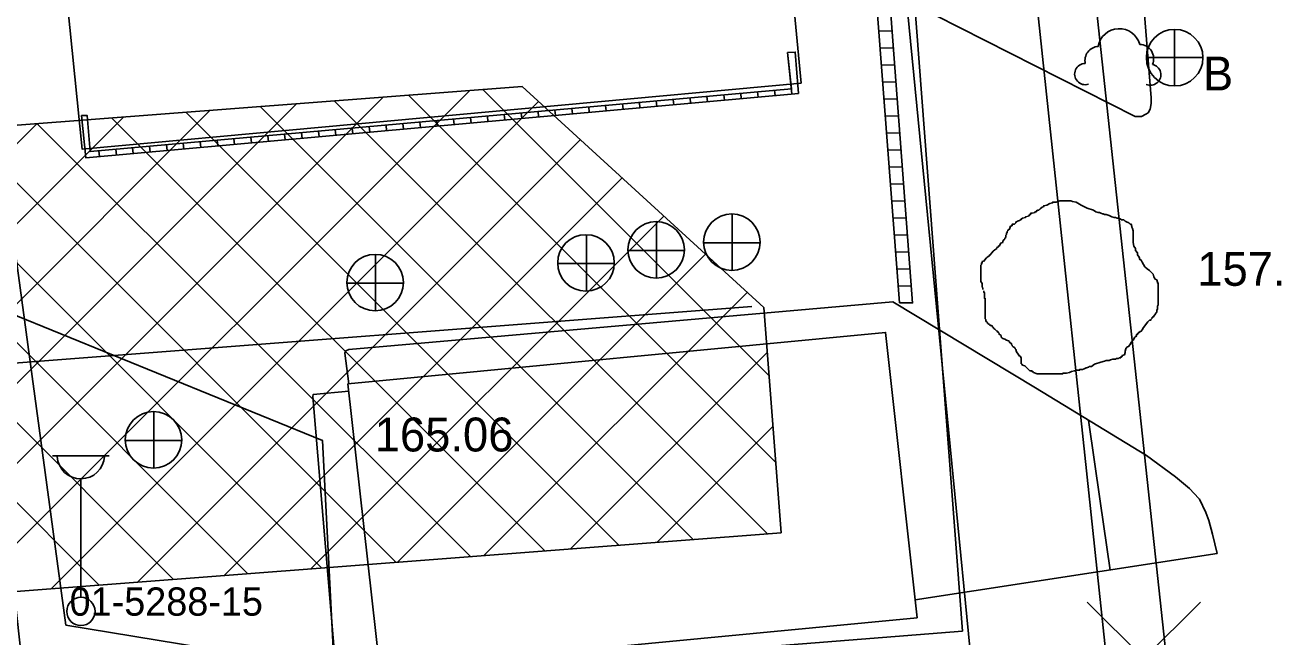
# Model space of a CAD drawing. Extents: x 419101 to 420177, y 4451541 to 4452254.
# Drawn here: x 419933.36 to 419977.69, y 4451769.46 to 4451791.12 of the extents above; entities that cross this region are included whole.
import ezdxf

# ---------------------------------------------------------------- set-up
doc = ezdxf.new("R2010")
doc.units = 0
for name, color, linetype in [('2_KADASTRO', 7, 'Continuous'), ('3_HALİHAZIR', 7, 'Continuous'), ('Level 10', 7, 'Continuous'), ('Level 15', 7, 'Continuous'), ('Level 20', 7, 'Continuous'), ('Level 28', 7, 'Continuous'), ('Level 3', 7, 'Continuous'), ('Level 62', 7, 'Continuous')]:
    doc.layers.add(name, color=color, linetype=linetype)

msp = doc.modelspace()

# ---------------------------------------------------------------- linework, layer by layer
at = {"layer": '2_KADASTRO'}
for points in [[(419929.599, 4451807.363), (419933.692, 4451807.567), (419933.672, 4451807.887), (419933.298, 4451813.605), (419932.726, 4451822.357), (419932.127, 4451831.536), (419932.103, 4451831.914), (419942.228, 4451832.442), (419960.444, 4451833.976), (419966.957, 4451767.405), (419964.966, 4451767.212), (419944.453, 4451765.219), (419944.306, 4451768.129), (419943.886, 4451776.419), (419932.776, 4451780.954), (419932.727, 4451781.361), (419929.891, 4451804.935)], [(419931.847, 4451781.334), (419932.776, 4451780.954), (419943.886, 4451776.419), (419944.306, 4451768.129), (419944.453, 4451765.219), (419933.727, 4451764.177)]]:
    msp.add_lwpolyline(points, close=True, dxfattribs=at)
at = {"layer": '3_HALİHAZIR'}
for p, q in [((419963.573, 4451790.915), (419964.038, 4451790.904)), ((419974.038, 4451790.97), (419974.038, 4451788.97)), ((419963.619, 4451790.314), (419964.082, 4451790.303)), ((419960.341, 4451790.149), (419960.498, 4451788.685)), ((419973.038, 4451789.97), (419975.038, 4451789.97)), ((419963.665, 4451789.712), (419964.127, 4451789.702)), ((419963.71, 4451789.111), (419964.172, 4451789.101)), ((419955.697, 4451788.438), (419955.717, 4451788.252)), ((419956.295, 4451788.492), (419956.314, 4451788.306)), ((419956.892, 4451788.545), (419956.912, 4451788.36)), ((419957.49, 4451788.599), (419957.51, 4451788.414)), ((419958.088, 4451788.653), (419958.107, 4451788.469)), ((419958.685, 4451788.706), (419958.705, 4451788.523)), ((419959.283, 4451788.76), (419959.303, 4451788.577)), ((419959.881, 4451788.813), (419959.9, 4451788.631)), ((419963.756, 4451788.51), (419964.217, 4451788.5)), ((419950.915, 4451788.01), (419950.936, 4451787.818)), ((419951.513, 4451788.064), (419951.533, 4451787.873)), ((419952.111, 4451788.117), (419952.131, 4451787.927)), ((419952.708, 4451788.171), (419952.729, 4451787.981)), ((419953.306, 4451788.224), (419953.326, 4451788.035)), ((419953.904, 4451788.278), (419953.924, 4451788.089)), ((419954.501, 4451788.331), (419954.522, 4451788.144)), ((419955.099, 4451788.385), (419955.119, 4451788.198)), ((419946.134, 4451787.582), (419946.155, 4451787.385)), ((419946.731, 4451787.635), (419946.752, 4451787.439)), ((419947.329, 4451787.689), (419947.35, 4451787.493)), ((419947.927, 4451787.742), (419947.948, 4451787.548)), ((419948.524, 4451787.796), (419948.545, 4451787.602)), ((419949.122, 4451787.849), (419949.143, 4451787.656)), ((419949.72, 4451787.903), (419949.74, 4451787.71)), ((419950.317, 4451787.957), (419950.338, 4451787.764)), ((419963.802, 4451787.909), (419964.262, 4451787.898)), ((419940.754, 4451787.1), (419940.776, 4451786.898)), ((419941.352, 4451787.153), (419941.374, 4451786.952)), ((419941.95, 4451787.207), (419941.971, 4451787.006)), ((419942.547, 4451787.261), (419942.569, 4451787.06)), ((419943.145, 4451787.314), (419943.166, 4451787.114)), ((419943.743, 4451787.368), (419943.764, 4451787.168)), ((419944.34, 4451787.421), (419944.362, 4451787.223)), ((419944.938, 4451787.475), (419944.959, 4451787.277)), ((419945.536, 4451787.528), (419945.557, 4451787.331)), ((419963.847, 4451787.308), (419964.307, 4451787.297)), ((419935.973, 4451786.672), (419935.995, 4451786.464)), ((419936.57, 4451786.725), (419936.592, 4451786.518)), ((419937.168, 4451786.779), (419937.19, 4451786.573)), ((419937.766, 4451786.832), (419937.788, 4451786.627)), ((419938.363, 4451786.886), (419938.385, 4451786.681)), ((419938.961, 4451786.939), (419938.983, 4451786.735)), ((419939.559, 4451786.993), (419939.581, 4451786.789)), ((419940.157, 4451787.046), (419940.178, 4451786.843)), ((419963.893, 4451786.706), (419964.352, 4451786.696)), ((419963.939, 4451786.105), (419964.397, 4451786.095)), ((419963.984, 4451785.504), (419964.442, 4451785.494)), ((419964.03, 4451784.903), (419964.487, 4451784.892)), ((419955.709, 4451782.158), (419955.709, 4451784.158)), ((419958.386, 4451782.43), (419958.386, 4451784.43)), ((419964.076, 4451784.302), (419964.532, 4451784.291)), ((419953.224, 4451781.695), (419953.224, 4451783.695)), ((419964.121, 4451783.7), (419964.577, 4451783.69)), ((419954.689, 4451783.148), (419956.689, 4451783.148)), ((419957.366, 4451783.42), (419959.366, 4451783.42)), ((419945.763, 4451780.999), (419945.763, 4451782.999)), ((419952.204, 4451782.685), (419954.204, 4451782.685)), ((419964.167, 4451783.099), (419964.622, 4451783.089)), ((419964.212, 4451782.498), (419964.667, 4451782.488)), ((419944.743, 4451781.989), (419946.743, 4451781.989)), ((419964.258, 4451781.897), (419964.712, 4451781.886)), ((419964.304, 4451781.296), (419964.757, 4451781.285)), ((419937.923, 4451775.431), (419937.923, 4451777.431)), ((419936.903, 4451776.421), (419938.903, 4451776.421)), ((419934.337, 4451775.869), (419936.337, 4451775.869)), ((419935.337, 4451770.869), (419935.337, 4451775.062)), ((419972.947, 4451768.698), (419970.947, 4451770.698)), ((419972.947, 4451768.698), (419974.957, 4451770.698))]:
    msp.add_line(p, q, dxfattribs=at)
for points in [[(419963.345, 4451815.509), (419967.105, 4451819.823), (419967.688, 4451820.448), (419967.944, 4451820.633), (419968.233, 4451820.728), (419968.62, 4451820.702), (419968.859, 4451820.612), (419968.996, 4451820.531), (419969.362, 4451820.015), (419969.437, 4451819.796), (419971.24, 4451810.117), (419972.263, 4451800.355), (419973.213, 4451788.552), (419973.204, 4451788.351), (419973.177, 4451788.142), (419973.101, 4451788.019), (419973.024, 4451787.966), (419972.862, 4451787.889), (419972.787, 4451787.883), (419972.638, 4451787.889), (419965.564, 4451791.473)], [(419945.897, 4451768.473), (419944.424, 4451768.303), (419934.808, 4451769.885), (419929.855, 4451806.414)], [(419944.823, 4451778.421), (419944.682, 4451779.504), (419944.699, 4451779.573), (419944.709, 4451779.587), (419944.818, 4451779.638), (419964.07, 4451781.33)], [(419964.07, 4451781.33), (419969.11, 4451778.285)], [(419969.11, 4451778.285), (419973.037, 4451775.891), (419974.071, 4451775.135), (419974.558, 4451774.716), (419974.893, 4451774.37), (419974.914, 4451774.338)], [(419944.353, 4451768.314), (419943.541, 4451777.978), (419943.558, 4451778.048), (419944.815, 4451778.164)], [(419971.397, 4451774.266), (419970.984, 4451777.143)], [(419971.397, 4451774.266), (419971.759, 4451771.831)], [(419975.544, 4451772.412), (419975.381, 4451773.103), (419975.252, 4451773.583), (419975.137, 4451773.869), (419974.914, 4451774.338)], [(419964.853, 4451770.771), (419975.544, 4451772.412)]]:
    msp.add_lwpolyline(points, dxfattribs=at)
for points in [[(419960.82, 4451789.064), (419959.183, 4451806.312), (419933.639, 4451803.973), (419935.388, 4451786.729)], [(419964.304, 4451781.294), (419964.757, 4451781.284), (419963.932, 4451792.31), (419963.469, 4451792.292)], [(419960.341, 4451790.149), (419960.614, 4451790.17), (419960.725, 4451788.706), (419935.515, 4451786.421), (419935.359, 4451787.92), (419935.556, 4451787.925), (419935.665, 4451786.644), (419960.478, 4451788.867)], [(419964.923, 4451770.135), (419963.81, 4451780.246), (419944.787, 4451778.418), (419945.914, 4451768.32)]]:
    msp.add_lwpolyline(points, close=True, dxfattribs=at)
for centre, radius in [((419974.038, 4451789.97), 1), ((419958.371, 4451783.438), 1), ((419955.693, 4451783.166), 1), ((419953.209, 4451782.703), 1), ((419945.748, 4451782.007), 1), ((419937.908, 4451776.439), 1), ((419935.337, 4451770.369), 0.5)]:
    msp.add_circle(centre, radius, dxfattribs=at)
for centre, radius, start, end in [((419972.075, 4451790.247), 0.75, 14.7016, 170.8724), ((419971.365, 4451789.867), 0.5, 93.3917, 192.0801), ((419972.795, 4451789.937), 0.5, 335.9144, 89.3104), ((419970.875, 4451789.387), 0.375, 89.7583, 287.6927), ((419973.175, 4451789.367), 0.375, 246.8223, 78.1035), ((419935.337, 4451775.899), 0.837, 183.298, 356.9072)]:
    msp.add_arc(centre, radius, start, end, dxfattribs=at)
at = {"layer": 'Level 10'}
msp.add_lwpolyline([(419958.201, 4451879.006), (419966.53, 4451769.671), (419931.06, 4451766.859), (419938.096, 4451697.79), (419879.097, 4451703.767), (419870.357, 4451698.446), (419851.433, 4451826.814), (419850.731, 4451885.176)], dxfattribs=at)
at = {"layer": 'Level 15'}
for p, q in [((419913.533, 4451756.076), (419946.03, 4451788.572)), ((419931.217, 4451770.931), (419949.094, 4451788.808)), ((419959.629, 4451773.113), (419944.302, 4451788.44)), ((419959.919, 4451775.651), (419946.929, 4451788.641)), ((419959.683, 4451778.715), (419949.555, 4451788.843)), ((419928.785, 4451774.157), (419942.966, 4451788.337)), ((419929.362, 4451777.562), (419939.902, 4451788.102)), ((419934.281, 4451771.166), (419951.53, 4451788.416)), ((419954.375, 4451772.71), (419939.048, 4451788.036)), ((419957.002, 4451772.911), (419941.675, 4451788.238)), ((419928.093, 4451781.949), (419933.775, 4451787.631)), ((419928.964, 4451779.992), (419936.839, 4451787.867)), ((419949.122, 4451772.306), (419933.795, 4451787.633)), ((419951.748, 4451772.508), (419936.422, 4451787.835)), ((419943.868, 4451771.903), (419928.542, 4451787.229)), ((419946.495, 4451772.104), (419931.168, 4451787.431)), ((419938.615, 4451771.499), (419923.288, 4451786.826)), ((419941.242, 4451771.701), (419925.915, 4451787.028)), ((419937.344, 4451771.402), (419953.008, 4451787.065)), ((419940.408, 4451771.637), (419954.485, 4451785.714)), ((419943.472, 4451771.872), (419955.962, 4451784.362)), ((419946.535, 4451772.108), (419957.439, 4451783.011)), ((419949.599, 4451772.343), (419958.916, 4451781.66)), ((419952.663, 4451772.578), (419959.62, 4451779.535)), ((419935.988, 4451771.298), (419929.345, 4451777.941)), ((419955.727, 4451772.813), (419959.822, 4451776.909))]:
    msp.add_line(p, q, dxfattribs=at)
at = {"layer": 'Level 20'}
msp.add_line((419959.078, 4451781.163), (419914.466, 4451777.736), dxfattribs=at)
at = {"layer": 'Level 28'}
msp.add_lwpolyline([(419925.866, 4451743.123), (419918.313, 4451725.295), (419910.947, 4451728.416), (419900.505, 4451744.786), (419905.594, 4451756.797), (419900.382, 4451765), (419908.773, 4451784.806), (419918.182, 4451785.792), (419918.133, 4451786.43), (419950.947, 4451788.95), (419959.498, 4451781.127), (419960.111, 4451773.15), (419928.884, 4451770.752), (419920.655, 4451751.326)], close=True, dxfattribs=at)
at = {"layer": 'Level 3'}
for points in [[(419969.512, 4451784.751), (419969.616, 4451784.803), (419969.719, 4451784.829), (419969.719, 4451784.855), (419969.745, 4451784.855), (419969.771, 4451784.855), (419969.849, 4451784.855), (419969.979, 4451784.907), (419970.083, 4451784.907), (419970.16, 4451784.907), (419970.212, 4451784.907), (419970.29, 4451784.907), (419970.342, 4451784.907), (419970.368, 4451784.907), (419970.42, 4451784.881), (419970.55, 4451784.855), (419970.731, 4451784.751), (419970.939, 4451784.647), (419971.172, 4451784.569), (419971.25, 4451784.517), (419971.328, 4451784.491), (419971.38, 4451784.491), (419971.432, 4451784.465), (419971.483, 4451784.439), (419971.509, 4451784.439), (419971.561, 4451784.413), (419971.613, 4451784.413), (419971.717, 4451784.387), (419971.821, 4451784.335), (419971.898, 4451784.309), (419971.95, 4451784.309), (419972.002, 4451784.283), (419972.054, 4451784.283), (419972.08, 4451784.283), (419972.158, 4451784.232), (419972.236, 4451784.232), (419972.288, 4451784.18), (419972.339, 4451784.154), (419972.417, 4451784.128), (419972.469, 4451784.076), (419972.495, 4451784.076), (419972.521, 4451783.998), (419972.521, 4451783.972), (419972.547, 4451783.92), (419972.573, 4451783.842), (419972.573, 4451783.816), (419972.573, 4451783.738), (419972.573, 4451783.686), (419972.573, 4451783.608), (419972.573, 4451783.582), (419972.573, 4451783.504), (419972.573, 4451783.427), (419972.599, 4451783.297), (419972.651, 4451783.219), (419972.651, 4451783.141), (419972.729, 4451783.063), (419972.729, 4451782.985), (419972.78, 4451782.907), (419972.806, 4451782.829), (419972.858, 4451782.803), (419972.884, 4451782.725), (419972.936, 4451782.647), (419972.988, 4451782.57), (419973.066, 4451782.492), (419973.144, 4451782.44), (419973.195, 4451782.388), (419973.221, 4451782.362), (419973.273, 4451782.31), (419973.299, 4451782.206), (419973.351, 4451782.128), (419973.403, 4451782.102), (419973.429, 4451782.024), (419973.429, 4451781.998), (419973.455, 4451781.998), (419973.455, 4451781.972), (419973.455, 4451781.946), (419973.455, 4451781.894), (419973.455, 4451781.791), (419973.455, 4451781.739), (419973.455, 4451781.661), (419973.455, 4451781.583), (419973.455, 4451781.505), (419973.455, 4451781.427), (419973.455, 4451781.349), (419973.455, 4451781.297), (419973.455, 4451781.219), (419973.429, 4451781.167), (419973.429, 4451781.063), (419973.403, 4451781.037), (419973.403, 4451780.96), (419973.377, 4451780.934), (419973.377, 4451780.908), (419973.325, 4451780.856), (419973.273, 4451780.778), (419973.247, 4451780.778), (419973.247, 4451780.752), (419973.221, 4451780.726), (419973.195, 4451780.7), (419973.195, 4451780.674), (419973.17, 4451780.674), (419973.144, 4451780.674)], [(419967.255, 4451781.765), (419967.255, 4451781.791), (419967.255, 4451781.816), (419967.229, 4451781.842), (419967.229, 4451781.868), (419967.229, 4451781.894), (419967.229, 4451781.92), (419967.229, 4451781.946), (419967.229, 4451781.972), (419967.177, 4451782.05), (419967.177, 4451782.128), (419967.177, 4451782.154), (419967.177, 4451782.232), (419967.177, 4451782.31), (419967.177, 4451782.336), (419967.177, 4451782.362), (419967.177, 4451782.388), (419967.177, 4451782.414), (419967.177, 4451782.44), (419967.177, 4451782.466), (419967.177, 4451782.492), (419967.177, 4451782.518), (419967.177, 4451782.544), (419967.177, 4451782.622), (419967.203, 4451782.647), (419967.203, 4451782.673), (419967.203, 4451782.699), (419967.229, 4451782.699), (419967.229, 4451782.725), (419967.229, 4451782.751), (419967.307, 4451782.777), (419967.307, 4451782.803), (419967.385, 4451782.881), (419967.437, 4451782.933), (419967.488, 4451782.959), (419967.488, 4451782.985), (419967.514, 4451782.985), (419967.566, 4451783.063), (419967.618, 4451783.115), (419967.67, 4451783.167), (419967.748, 4451783.219), (419967.748, 4451783.245), (419967.8, 4451783.271), (419967.8, 4451783.297), (419967.826, 4451783.297), (419967.878, 4451783.375), (419967.878, 4451783.401), (419967.955, 4451783.427), (419967.955, 4451783.452), (419967.955, 4451783.478), (419968.007, 4451783.53), (419968.033, 4451783.556), (419968.033, 4451783.582), (419968.059, 4451783.608), (419968.059, 4451783.634), (419968.059, 4451783.66), (419968.059, 4451783.686), (419968.085, 4451783.712), (419968.085, 4451783.738), (419968.085, 4451783.764), (419968.111, 4451783.764), (419968.111, 4451783.79), (419968.111, 4451783.816), (419968.137, 4451783.842), (419968.137, 4451783.868), (419968.189, 4451783.894), (419968.215, 4451783.972), (419968.215, 4451783.998), (419968.293, 4451784.024), (419968.293, 4451784.05), (419968.293, 4451784.076), (419968.37, 4451784.076), (419968.422, 4451784.128), (419968.422, 4451784.154), (419968.448, 4451784.154), (419968.474, 4451784.18), (419968.552, 4451784.206), (419968.578, 4451784.232), (419968.604, 4451784.232), (419968.604, 4451784.258), (419968.656, 4451784.283), (419968.76, 4451784.309), (419968.76, 4451784.335), (419968.863, 4451784.361), (419968.915, 4451784.413), (419968.941, 4451784.413), (419968.941, 4451784.439), (419968.941, 4451784.465), (419968.993, 4451784.465), (419969.097, 4451784.491), (419969.097, 4451784.517), (419969.123, 4451784.517), (419969.149, 4451784.517), (419969.149, 4451784.543), (419969.201, 4451784.569), (419969.227, 4451784.569), (419969.278, 4451784.621), (419969.356, 4451784.673), (419969.408, 4451784.699), (419969.408, 4451784.725), (419969.512, 4451784.751)], [(419969.201, 4451778.778), (419969.175, 4451778.778), (419969.045, 4451778.83), (419969.019, 4451778.856), (419968.993, 4451778.856), (419968.993, 4451778.882), (419968.915, 4451778.882), (419968.863, 4451778.934), (419968.786, 4451779.012), (419968.734, 4451779.064), (419968.656, 4451779.09), (419968.63, 4451779.116), (419968.604, 4451779.142), (419968.604, 4451779.168), (419968.604, 4451779.246), (419968.604, 4451779.324), (419968.604, 4451779.349), (419968.578, 4451779.375), (419968.578, 4451779.401), (419968.552, 4451779.401), (419968.5, 4451779.479), (419968.448, 4451779.557), (419968.422, 4451779.635), (419968.396, 4451779.661), (419968.396, 4451779.687), (419968.37, 4451779.713), (419968.319, 4451779.739), (419968.293, 4451779.765), (419968.293, 4451779.791), (419968.267, 4451779.817), (419968.267, 4451779.843), (419968.189, 4451779.895), (419968.189, 4451779.921), (419968.163, 4451779.947), (419968.085, 4451779.973), (419968.033, 4451779.999), (419967.955, 4451780.025), (419967.929, 4451780.051), (419967.904, 4451780.077), (419967.904, 4451780.103), (419967.904, 4451780.129), (419967.826, 4451780.18), (419967.826, 4451780.206), (419967.8, 4451780.232), (419967.8, 4451780.258), (419967.774, 4451780.258), (419967.774, 4451780.284), (419967.748, 4451780.284), (419967.722, 4451780.31), (419967.696, 4451780.336), (419967.67, 4451780.362), (419967.644, 4451780.388), (419967.618, 4451780.414), (419967.592, 4451780.44), (419967.592, 4451780.466), (419967.54, 4451780.492), (419967.514, 4451780.492), (419967.488, 4451780.518), (419967.437, 4451780.544), (419967.411, 4451780.57), (419967.411, 4451780.596), (419967.385, 4451780.622), (419967.359, 4451780.648), (419967.359, 4451780.674), (419967.359, 4451780.7), (419967.333, 4451780.726), (419967.333, 4451780.752), (419967.333, 4451780.778), (419967.333, 4451780.856), (419967.333, 4451780.908), (419967.333, 4451780.934), (419967.333, 4451780.96), (419967.333, 4451780.985), (419967.333, 4451781.011), (419967.333, 4451781.037), (419967.333, 4451781.063), (419967.333, 4451781.089), (419967.333, 4451781.115), (419967.333, 4451781.141), (419967.333, 4451781.167), (419967.333, 4451781.193), (419967.333, 4451781.219), (419967.333, 4451781.245), (419967.333, 4451781.271), (419967.333, 4451781.297), (419967.333, 4451781.323), (419967.333, 4451781.401), (419967.333, 4451781.427), (419967.333, 4451781.453), (419967.307, 4451781.453), (419967.307, 4451781.479), (419967.307, 4451781.505), (419967.307, 4451781.531), (419967.307, 4451781.557), (419967.307, 4451781.583), (419967.307, 4451781.609), (419967.307, 4451781.635), (419967.307, 4451781.661), (419967.281, 4451781.661), (419967.281, 4451781.687), (419967.281, 4451781.713)], [(419973.144, 4451780.674), (419973.092, 4451780.622), (419972.936, 4451780.414), (419972.884, 4451780.336), (419972.858, 4451780.284), (419972.832, 4451780.284), (419972.806, 4451780.258), (419972.78, 4451780.258), (419972.78, 4451780.232), (419972.754, 4451780.232), (419972.754, 4451780.206), (419972.729, 4451780.206), (419972.729, 4451780.18), (419972.703, 4451780.18), (419972.677, 4451780.103), (419972.651, 4451780.103), (419972.625, 4451780.077), (419972.573, 4451779.973), (419972.495, 4451779.895), (419972.469, 4451779.817), (419972.391, 4451779.739), (419972.365, 4451779.739), (419972.339, 4451779.713), (419972.339, 4451779.687), (419972.313, 4451779.687), (419972.313, 4451779.661), (419972.288, 4451779.583), (419972.288, 4451779.531), (419972.262, 4451779.453), (419972.184, 4451779.427), (419972.184, 4451779.401), (419972.158, 4451779.401), (419972.158, 4451779.375), (419972.132, 4451779.375), (419972.132, 4451779.349), (419972.106, 4451779.349), (419972.08, 4451779.349), (419972.054, 4451779.324), (419972.028, 4451779.324), (419972.002, 4451779.324), (419971.976, 4451779.324), (419971.95, 4451779.298), (419971.924, 4451779.298), (419971.898, 4451779.298), (419971.872, 4451779.298), (419971.847, 4451779.298), (419971.769, 4451779.272), (419971.717, 4451779.246), (419971.639, 4451779.246), (419971.613, 4451779.246), (419971.561, 4451779.22), (419971.432, 4451779.194), (419971.198, 4451779.116), (419971.094, 4451779.038), (419971.016, 4451779.038), (419970.991, 4451779.012), (419970.965, 4451779.012), (419970.939, 4451778.986), (419970.913, 4451778.986), (419970.835, 4451778.96), (419970.783, 4451778.934), (419970.757, 4451778.934), (419970.731, 4451778.934), (419970.705, 4451778.934), (419970.679, 4451778.934), (419970.679, 4451778.908), (419970.653, 4451778.908), (419970.627, 4451778.908), (419970.55, 4451778.908), (419970.498, 4451778.882), (419970.394, 4451778.856), (419970.316, 4451778.83), (419970.212, 4451778.804), (419970.16, 4451778.804), (419970.134, 4451778.804), (419970.109, 4451778.804), (419970.083, 4451778.804), (419970.083, 4451778.778), (419970.057, 4451778.778), (419970.031, 4451778.778), (419970.005, 4451778.778), (419969.979, 4451778.778), (419969.953, 4451778.778), (419969.927, 4451778.778), (419969.901, 4451778.778), (419969.875, 4451778.778), (419969.849, 4451778.778), (419969.771, 4451778.778), (419969.719, 4451778.778), (419969.642, 4451778.778), (419969.59, 4451778.778), (419969.564, 4451778.778), (419969.538, 4451778.778), (419969.486, 4451778.778), (419969.408, 4451778.778), (419969.382, 4451778.778), (419969.33, 4451778.778), (419969.304, 4451778.778), (419969.252, 4451778.778), (419969.227, 4451778.778), (419969.201, 4451778.778)]]:
    msp.add_lwpolyline(points, dxfattribs=at)
at = {"layer": 'Level 62'}
for p, q in [((419978.89, 4451720.803), (419969.414, 4451808.991)), ((419968.536, 4451797.726), (419975.494, 4451732.407))]:
    msp.add_line(p, q, dxfattribs=at)

# ---------------------------------------------------------------- texts
at = {"layer": '2_KADASTRO'}
msp.add_text('01-5288-15', height=1, dxfattribs=at).set_placement((419934.938, 4451770.216))
at = {"layer": '3_HALİHAZIR'}
msp.add_text('B', height=1.2, dxfattribs=at).set_placement((419975.038, 4451788.809))
for s, rotation, p in [('157.53 ', 359.9971, (419974.84, 4451781.894)), ('165.06 ', 359.9979, (419945.734, 4451776.029))]:
    msp.add_text(s, height=1.2, rotation=rotation, dxfattribs=at).set_placement(p)

doc.saveas('drawing.dxf')
